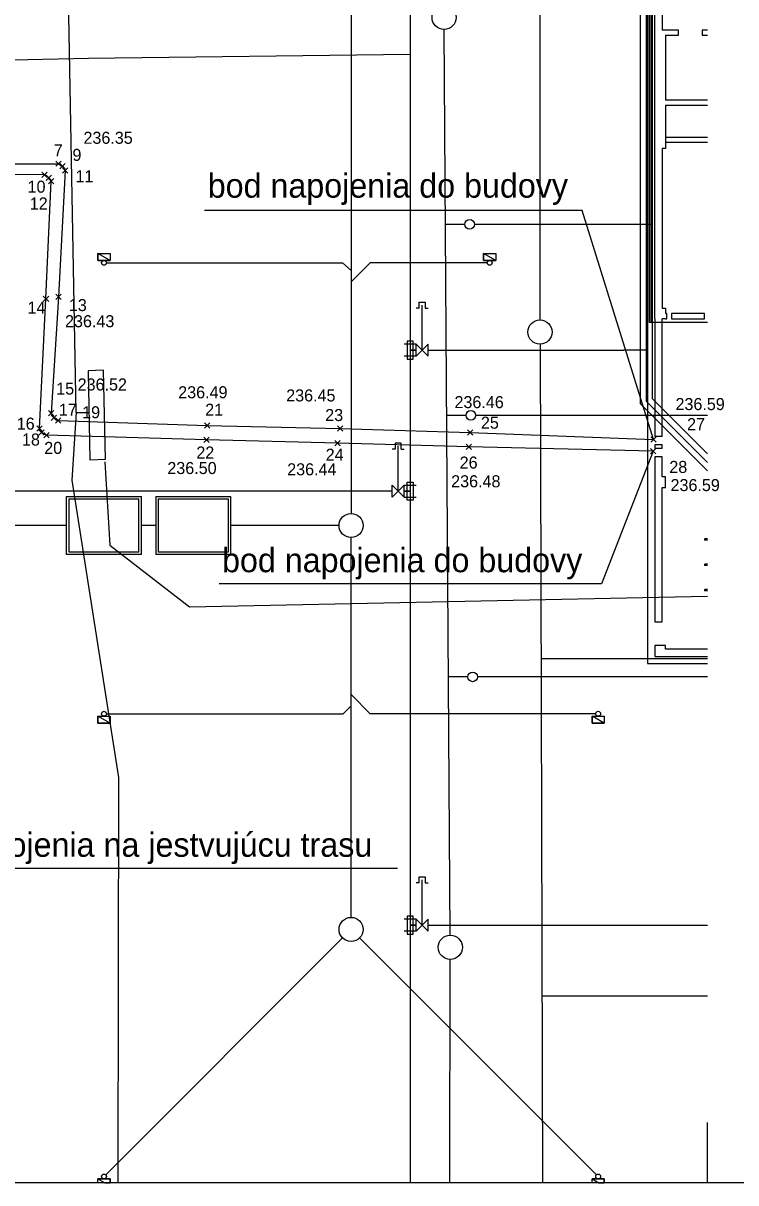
# Model space of a CAD drawing. Extents: x -263964 to -263859, y -1242287 to -1242158.
# Drawn here: x -263940.2 to -263910.63, y -1242232.02 to -1242183.91 of the extents above; entities that cross this region are included whole.
import ezdxf

# ---------------------------------------------------------------- set-up
doc = ezdxf.new("R2010")
doc.units = 0
for name, color, linetype in [('BODY_SYMBOL_A_CISLO', 7, 'Continuous'), ('BODY_VYSKA', 7, 'Continuous'), ('KFA_2D_JESTVUJUCE_IS_DSP', 7, 'Continuous'), ('KFA_2D_SITUACIA_DSP', 7, 'Continuous'), ('KFA_BETONY_HL_B_1PP', 7, 'Continuous'), ('KFA_SO_80-1_HORUCOVOD_TRASA', 7, 'Continuous'), ('POPIS', 7, 'Continuous'), ('RAM_NA_TLAC_A3_1-250', 7, 'Continuous')]:
    doc.layers.add(name, color=color, linetype=linetype)

msp = doc.modelspace()

# ---------------------------------------------------------------- linework, layer by layer
at = {"layer": 'BODY_SYMBOL_A_CISLO'}
for p, q in [((-263938.84, -1242189.85), (-263938.619, -1242189.63)), ((-263938.619, -1242189.85), (-263938.84, -1242189.63)), ((-263938.671, -1242189.951), (-263938.449, -1242189.73)), ((-263938.449, -1242189.951), (-263938.671, -1242189.73)), ((-263938.571, -1242190.13), (-263938.35, -1242189.91)), ((-263938.35, -1242190.13), (-263938.571, -1242189.91)), ((-263939.421, -1242190.311), (-263939.199, -1242190.09)), ((-263939.199, -1242190.311), (-263939.421, -1242190.09)), ((-263939.241, -1242190.441), (-263939.019, -1242190.22)), ((-263939.019, -1242190.441), (-263939.241, -1242190.22)), ((-263939.15, -1242190.58), (-263938.929, -1242190.36)), ((-263938.929, -1242190.58), (-263939.15, -1242190.36)), ((-263939.361, -1242195.458), (-263939.139, -1242195.237)), ((-263939.139, -1242195.458), (-263939.361, -1242195.237)), ((-263938.845, -1242195.382), (-263938.625, -1242195.16)), ((-263938.625, -1242195.382), (-263938.845, -1242195.16)), ((-263939.141, -1242200.201), (-263938.92, -1242199.98)), ((-263938.92, -1242200.201), (-263939.141, -1242199.98)), ((-263939.041, -1242200.39), (-263938.819, -1242200.17)), ((-263938.819, -1242200.39), (-263939.041, -1242200.17)), ((-263939.631, -1242200.84), (-263939.41, -1242200.62)), ((-263939.41, -1242200.84), (-263939.631, -1242200.62)), ((-263938.861, -1242200.511), (-263938.639, -1242200.289)), ((-263938.639, -1242200.511), (-263938.861, -1242200.289)), ((-263932.681, -1242200.711), (-263932.459, -1242200.49)), ((-263932.459, -1242200.711), (-263932.681, -1242200.49)), ((-263927.15, -1242200.84), (-263926.929, -1242200.62)), ((-263926.929, -1242200.84), (-263927.15, -1242200.62)), ((-263939.541, -1242201.011), (-263939.319, -1242200.789)), ((-263939.319, -1242201.011), (-263939.541, -1242200.789)), ((-263939.34, -1242201.11), (-263939.119, -1242200.89)), ((-263939.119, -1242201.11), (-263939.34, -1242200.89)), ((-263932.701, -1242201.311), (-263932.48, -1242201.09)), ((-263932.48, -1242201.311), (-263932.701, -1242201.09)), ((-263921.761, -1242201.011), (-263921.54, -1242200.789)), ((-263921.54, -1242201.011), (-263921.761, -1242200.789)), ((-263914.16, -1242201.301), (-263913.939, -1242201.079)), ((-263913.939, -1242201.301), (-263914.16, -1242201.079)), ((-263927.27, -1242201.451), (-263927.049, -1242201.23)), ((-263927.049, -1242201.451), (-263927.27, -1242201.23)), ((-263921.821, -1242201.6), (-263921.6, -1242201.38)), ((-263921.6, -1242201.6), (-263921.821, -1242201.38)), ((-263914.171, -1242201.781), (-263913.949, -1242201.559)), ((-263913.949, -1242201.781), (-263914.171, -1242201.559))]:
    msp.add_line(p, q, dxfattribs=at)
at = {"layer": 'KFA_2D_JESTVUJUCE_IS_DSP'}
for p, q in [((-263937.993, -1242200.068), (-263938.781, -1242157.773)), ((-263918.763, -1242157.773), (-263918.757, -1242196.225)), ((-263922.479, -1242221.753), (-263922.731, -1242184.174)), ((-263937.488, -1242185.363), (-263924.143, -1242185.192)), ((-263952.832, -1242185.692), (-263937.488, -1242185.363)), ((-263918.755, -1242197.225), (-263918.646, -1242232.023)), ((-263936.861, -1242198.305), (-263937.501, -1242198.334)), ((-263937.501, -1242198.334), (-263937.428, -1242202.028)), ((-263937.501, -1242198.334), (-263937.501, -1242198.334)), ((-263936.776, -1242202.003), (-263936.861, -1242198.305)), ((-263937.993, -1242200.068), (-263938.174, -1242202.878)), ((-263937.993, -1242200.068), (-263937.467, -1242200.068)), ((-263937.428, -1242202.028), (-263936.776, -1242202.003)), ((-263936.81, -1242202.117), (-263936.602, -1242205.569)), ((-263938.174, -1242202.878), (-263936.242, -1242215.207)), ((-263936.602, -1242205.569), (-263933.291, -1242208.127)), ((-263933.291, -1242208.127), (-263911.807, -1242207.682)), ((-263936.242, -1242215.207), (-263936.275, -1242232.023)), ((-263922.497, -1242232.023), (-263922.477, -1242222.753))]:
    msp.add_line(p, q, dxfattribs=at)
for centre in [(-263922.734, -1242183.674), (-263918.757, -1242196.725), (-263922.476, -1242222.253)]:
    msp.add_circle(centre, 0.5, dxfattribs=at)
at = {"layer": 'KFA_2D_SITUACIA_DSP'}
for p, q in [((-263926.593, -1242157.773), (-263926.593, -1242204.252)), ((-263924.143, -1242157.773), (-263924.143, -1242185.14)), ((-263914.218, -1242196.332), (-263914.218, -1242157.773)), ((-263914.143, -1242196.333), (-263914.143, -1242157.773)), ((-263914.6, -1242168.728), (-263914.6, -1242199.693)), ((-263914.35, -1242168.625), (-263914.35, -1242199.59)), ((-263914.1, -1242168.521), (-263914.1, -1242199.486)), ((-263914.293, -1242175.482), (-263914.293, -1242210.482)), ((-263924.143, -1242185.14), (-263924.143, -1242232.023)), ((-263921.877, -1242192.257), (-263922.677, -1242192.257)), ((-263915.293, -1242192.257), (-263921.477, -1242192.257)), ((-263914.143, -1242192.257), (-263915.293, -1242192.257)), ((-263937.093, -1242193.752), (-263937.093, -1242193.462)), ((-263937.093, -1242193.462), (-263936.593, -1242193.462)), ((-263936.593, -1242193.752), (-263937.093, -1242193.462)), ((-263936.593, -1242193.752), (-263937.093, -1242193.462)), ((-263937.093, -1242193.462), (-263937.093, -1242193.752)), ((-263936.593, -1242193.752), (-263937.093, -1242193.752)), ((-263937.093, -1242193.752), (-263936.593, -1242193.752)), ((-263936.743, -1242193.852), (-263926.953, -1242193.852)), ((-263936.593, -1242193.462), (-263936.593, -1242193.752)), ((-263926.953, -1242193.852), (-263926.593, -1242194.178)), ((-263925.798, -1242193.852), (-263926.593, -1242194.648)), ((-263920.944, -1242193.852), (-263925.798, -1242193.852)), ((-263921.093, -1242193.752), (-263921.093, -1242193.462)), ((-263921.093, -1242193.462), (-263920.593, -1242193.462)), ((-263920.593, -1242193.752), (-263921.093, -1242193.462)), ((-263920.593, -1242193.752), (-263921.093, -1242193.462)), ((-263921.093, -1242193.462), (-263921.093, -1242193.752)), ((-263920.593, -1242193.752), (-263921.093, -1242193.752)), ((-263921.093, -1242193.752), (-263920.593, -1242193.752)), ((-263920.593, -1242193.462), (-263920.593, -1242193.752)), ((-263923.768, -1242195.732), (-263923.893, -1242195.732)), ((-263923.768, -1242195.732), (-263923.768, -1242195.482)), ((-263923.768, -1242195.482), (-263923.518, -1242195.482)), ((-263923.643, -1242197.482), (-263923.643, -1242195.607)), ((-263923.518, -1242195.482), (-263923.518, -1242195.732)), ((-263923.518, -1242195.732), (-263923.393, -1242195.732)), ((-263911.807, -1242196.332), (-263914.218, -1242196.332)), ((-263911.807, -1242196.333), (-263914.143, -1242196.333)), ((-263923.893, -1242197.232), (-263924.393, -1242197.232)), ((-263924.018, -1242197.107), (-263924.268, -1242197.107)), ((-263924.268, -1242197.107), (-263924.268, -1242197.857)), ((-263924.018, -1242197.857), (-263924.018, -1242197.107)), ((-263923.893, -1242197.732), (-263923.893, -1242197.232)), ((-263923.893, -1242197.232), (-263923.393, -1242197.732)), ((-263923.393, -1242197.232), (-263923.893, -1242197.732)), ((-263923.393, -1242197.732), (-263923.393, -1242197.232)), ((-263923.893, -1242197.732), (-263924.393, -1242197.732)), ((-263924.143, -1242197.482), (-263923.893, -1242197.482)), ((-263923.893, -1242197.482), (-263924.143, -1242197.482)), ((-263923.393, -1242197.482), (-263915.293, -1242197.482)), ((-263914.293, -1242197.482), (-263915.293, -1242197.482)), ((-263924.268, -1242197.857), (-263924.018, -1242197.857)), ((-263914.6, -1242199.693), (-263911.807, -1242202.486)), ((-263914.35, -1242199.59), (-263911.807, -1242202.133)), ((-263914.1, -1242199.486), (-263911.807, -1242201.779)), ((-263921.824, -1242200.182), (-263922.624, -1242200.182)), ((-263915.293, -1242200.182), (-263921.424, -1242200.182)), ((-263911.807, -1242200.182), (-263915.293, -1242200.182)), ((-263924.768, -1242201.582), (-263924.893, -1242201.582)), ((-263924.768, -1242201.332), (-263924.768, -1242201.582)), ((-263924.518, -1242201.332), (-263924.768, -1242201.332)), ((-263924.643, -1242203.332), (-263924.643, -1242201.457)), ((-263924.518, -1242201.582), (-263924.518, -1242201.332)), ((-263924.518, -1242201.582), (-263924.393, -1242201.582)), ((-263924.268, -1242203.707), (-263924.268, -1242202.957)), ((-263924.268, -1242202.957), (-263924.018, -1242202.957)), ((-263924.018, -1242202.957), (-263924.018, -1242203.707)), ((-263924.893, -1242203.332), (-263958.097, -1242203.332)), ((-263938.393, -1242203.552), (-263935.293, -1242203.552)), ((-263938.393, -1242205.952), (-263938.393, -1242203.552)), ((-263935.293, -1242205.952), (-263935.293, -1242203.552)), ((-263934.693, -1242203.552), (-263931.593, -1242203.552)), ((-263934.693, -1242203.552), (-263934.693, -1242205.952)), ((-263931.593, -1242203.552), (-263931.593, -1242205.952)), ((-263924.893, -1242203.582), (-263924.893, -1242203.082)), ((-263924.393, -1242203.082), (-263924.893, -1242203.582)), ((-263924.893, -1242203.082), (-263924.393, -1242203.582)), ((-263924.393, -1242203.582), (-263924.393, -1242203.082)), ((-263924.393, -1242203.082), (-263923.893, -1242203.082)), ((-263924.143, -1242203.332), (-263924.393, -1242203.332)), ((-263924.393, -1242203.332), (-263924.143, -1242203.332)), ((-263938.293, -1242205.852), (-263938.293, -1242203.652)), ((-263938.293, -1242203.652), (-263935.393, -1242203.652)), ((-263935.393, -1242205.852), (-263935.393, -1242203.652)), ((-263934.593, -1242203.652), (-263934.593, -1242205.852)), ((-263934.593, -1242203.652), (-263931.693, -1242203.652)), ((-263931.693, -1242203.652), (-263931.693, -1242205.852)), ((-263924.393, -1242203.582), (-263923.893, -1242203.582)), ((-263924.018, -1242203.707), (-263924.268, -1242203.707)), ((-263938.393, -1242204.752), (-263942.945, -1242204.752)), ((-263934.693, -1242204.752), (-263935.293, -1242204.752)), ((-263927.093, -1242204.752), (-263931.593, -1242204.752)), ((-263926.593, -1242221.011), (-263926.593, -1242205.252)), ((-263911.807, -1242205.307), (-263911.913, -1242205.307)), ((-263911.807, -1242205.357), (-263911.913, -1242205.357)), ((-263935.293, -1242205.952), (-263938.393, -1242205.952)), ((-263935.393, -1242205.852), (-263938.293, -1242205.852)), ((-263931.593, -1242205.952), (-263934.693, -1242205.952)), ((-263931.693, -1242205.852), (-263934.593, -1242205.852)), ((-263911.807, -1242206.358), (-263911.913, -1242206.358)), ((-263911.807, -1242206.408), (-263911.913, -1242206.408)), ((-263911.807, -1242207.409), (-263911.913, -1242207.409)), ((-263911.807, -1242207.459), (-263911.913, -1242207.459)), ((-263911.807, -1242210.282), (-263918.714, -1242210.282)), ((-263914.293, -1242210.482), (-263911.807, -1242210.482)), ((-263921.751, -1242211.032), (-263922.551, -1242211.032)), ((-263911.807, -1242211.032), (-263921.351, -1242211.032)), ((-263925.798, -1242212.562), (-263926.593, -1242211.767)), ((-263937.093, -1242212.952), (-263937.093, -1242212.662)), ((-263937.093, -1242212.662), (-263936.593, -1242212.662)), ((-263936.593, -1242212.952), (-263937.093, -1242212.662)), ((-263936.593, -1242212.952), (-263937.093, -1242212.662)), ((-263937.093, -1242212.662), (-263937.093, -1242212.952)), ((-263936.743, -1242212.562), (-263926.919, -1242212.562)), ((-263936.593, -1242212.662), (-263936.593, -1242212.952)), ((-263926.919, -1242212.562), (-263926.593, -1242212.237)), ((-263916.443, -1242212.562), (-263925.798, -1242212.562)), ((-263916.593, -1242212.952), (-263916.593, -1242212.662)), ((-263916.593, -1242212.662), (-263916.093, -1242212.662)), ((-263916.093, -1242212.952), (-263916.593, -1242212.662)), ((-263916.093, -1242212.952), (-263916.593, -1242212.662)), ((-263916.593, -1242212.662), (-263916.593, -1242212.952)), ((-263916.093, -1242212.662), (-263916.093, -1242212.952)), ((-263936.593, -1242212.952), (-263937.093, -1242212.952)), ((-263937.093, -1242212.952), (-263936.593, -1242212.952)), ((-263916.093, -1242212.952), (-263916.593, -1242212.952)), ((-263916.593, -1242212.952), (-263916.093, -1242212.952)), ((-263923.768, -1242219.582), (-263923.768, -1242219.332)), ((-263923.768, -1242219.332), (-263923.518, -1242219.332)), ((-263923.518, -1242219.332), (-263923.518, -1242219.582)), ((-263923.768, -1242219.582), (-263923.893, -1242219.582)), ((-263923.643, -1242221.332), (-263923.643, -1242219.457)), ((-263923.518, -1242219.582), (-263923.393, -1242219.582)), ((-263923.893, -1242221.082), (-263924.393, -1242221.082)), ((-263924.018, -1242220.957), (-263924.268, -1242220.957)), ((-263924.268, -1242220.957), (-263924.268, -1242221.707)), ((-263924.143, -1242221.332), (-263923.893, -1242221.332)), ((-263923.893, -1242221.332), (-263924.143, -1242221.332)), ((-263924.018, -1242221.707), (-263924.018, -1242220.957)), ((-263923.893, -1242221.582), (-263923.893, -1242221.082)), ((-263923.893, -1242221.082), (-263923.393, -1242221.582)), ((-263923.393, -1242221.082), (-263923.893, -1242221.582)), ((-263923.393, -1242221.582), (-263923.393, -1242221.082)), ((-263923.393, -1242221.332), (-263911.807, -1242221.332)), ((-263923.893, -1242221.582), (-263924.393, -1242221.582)), ((-263924.268, -1242221.707), (-263924.018, -1242221.707)), ((-263936.772, -1242231.691), (-263926.947, -1242221.865)), ((-263916.414, -1242231.691), (-263926.24, -1242221.865)), ((-263911.807, -1242224.282), (-263918.67, -1242224.282)), ((-263937.093, -1242231.862), (-263936.593, -1242231.862)), ((-263937.093, -1242232.023), (-263937.093, -1242231.862)), ((-263937.093, -1242231.862), (-263936.814, -1242232.023)), ((-263936.593, -1242231.862), (-263937.093, -1242231.862)), ((-263937.093, -1242231.862), (-263936.814, -1242232.023)), ((-263936.593, -1242231.862), (-263936.593, -1242232.023)), ((-263936.593, -1242232.023), (-263936.593, -1242231.862)), ((-263916.593, -1242231.862), (-263916.093, -1242231.862)), ((-263916.593, -1242232.023), (-263916.593, -1242231.862)), ((-263916.593, -1242231.862), (-263916.314, -1242232.023)), ((-263916.093, -1242231.862), (-263916.593, -1242231.862)), ((-263916.593, -1242231.862), (-263916.314, -1242232.023)), ((-263916.093, -1242231.862), (-263916.093, -1242232.023)), ((-263916.093, -1242232.023), (-263916.093, -1242231.862)), ((-263936.814, -1242232.023), (-263936.593, -1242232.023)), ((-263916.314, -1242232.023), (-263916.093, -1242232.023))]:
    msp.add_line(p, q, dxfattribs=at)
for centre, radius in [((-263921.677, -1242192.257), 0.2), ((-263936.843, -1242193.852), 0.1), ((-263920.844, -1242193.852), 0.1), ((-263921.624, -1242200.182), 0.2), ((-263926.593, -1242204.752), 0.5), ((-263921.551, -1242211.032), 0.2), ((-263936.843, -1242212.562), 0.1), ((-263916.343, -1242212.562), 0.1), ((-263926.593, -1242221.511), 0.5), ((-263936.843, -1242231.762), 0.1), ((-263916.343, -1242231.762), 0.1)]:
    msp.add_circle(centre, radius, dxfattribs=at)
for centre, start, end in [((-263911.913, -1242205.332), 90, 270), ((-263911.913, -1242206.383), 90, 180), ((-263911.913, -1242206.383), 180, 270), ((-263911.913, -1242207.434), 90, 270)]:
    msp.add_arc(centre, 0.025, start, end, dxfattribs=at)
at = {"layer": 'KFA_BETONY_HL_B_1PP'}
for p, q in [((-263913.993, -1242188.657), (-263913.993, -1242182.107)), ((-263913.693, -1242182.107), (-263913.693, -1242184.207)), ((-263913.013, -1242184.207), (-263913.693, -1242184.207)), ((-263913.013, -1242184.407), (-263913.013, -1242184.207)), ((-263912.033, -1242184.207), (-263912.033, -1242184.407)), ((-263911.807, -1242184.207), (-263912.033, -1242184.207)), ((-263913.543, -1242184.407), (-263913.543, -1242187.107)), ((-263913.543, -1242184.407), (-263913.013, -1242184.407)), ((-263912.033, -1242184.407), (-263911.807, -1242184.407)), ((-263911.807, -1242187.107), (-263913.543, -1242187.107)), ((-263913.543, -1242187.307), (-263911.807, -1242187.307)), ((-263913.543, -1242187.307), (-263913.543, -1242188.657)), ((-263913.993, -1242189.107), (-263913.993, -1242188.657)), ((-263913.993, -1242195.732), (-263913.993, -1242189.107)), ((-263913.543, -1242189.107), (-263913.693, -1242189.107)), ((-263913.693, -1242189.107), (-263913.693, -1242195.732)), ((-263911.807, -1242188.657), (-263913.543, -1242188.657)), ((-263913.543, -1242188.657), (-263913.543, -1242189.107)), ((-263911.807, -1242188.857), (-263913.543, -1242188.857)), ((-263913.993, -1242196.182), (-263913.993, -1242195.732)), ((-263913.693, -1242195.732), (-263913.543, -1242195.732)), ((-263913.543, -1242195.732), (-263913.543, -1242195.957)), ((-263913.993, -1242196.182), (-263913.993, -1242196.182)), ((-263913.993, -1242196.182), (-263913.993, -1242197.407)), ((-263913.543, -1242196.182), (-263913.693, -1242196.182)), ((-263913.693, -1242197.407), (-263913.693, -1242196.182)), ((-263913.495, -1242195.957), (-263913.543, -1242195.957)), ((-263913.543, -1242196.182), (-263913.495, -1242196.182)), ((-263913.495, -1242196.182), (-263913.495, -1242195.957)), ((-263913.295, -1242195.957), (-263913.295, -1242196.182)), ((-263911.934, -1242195.957), (-263913.295, -1242195.957)), ((-263913.295, -1242196.182), (-263911.934, -1242196.182)), ((-263911.934, -1242196.182), (-263911.934, -1242195.957)), ((-263913.993, -1242197.407), (-263913.993, -1242197.557)), ((-263913.993, -1242197.557), (-263913.993, -1242201.057)), ((-263913.693, -1242197.557), (-263913.693, -1242197.407)), ((-263913.693, -1242201.057), (-263913.693, -1242197.557)), ((-263913.693, -1242201.057), (-263913.993, -1242201.057)), ((-263913.693, -1242201.407), (-263913.993, -1242201.407)), ((-263913.993, -1242201.407), (-263913.993, -1242201.557)), ((-263913.693, -1242201.557), (-263913.993, -1242201.557)), ((-263913.693, -1242201.557), (-263913.693, -1242201.407)), ((-263913.693, -1242201.907), (-263913.993, -1242201.907)), ((-263913.993, -1242201.907), (-263913.993, -1242202.732)), ((-263913.693, -1242202.732), (-263913.693, -1242201.907)), ((-263913.993, -1242202.732), (-263913.993, -1242203.182)), ((-263913.543, -1242202.732), (-263913.693, -1242202.732)), ((-263913.543, -1242203.182), (-263913.543, -1242202.732)), ((-263913.993, -1242203.182), (-263913.993, -1242208.742)), ((-263913.693, -1242203.182), (-263913.543, -1242203.182)), ((-263913.693, -1242208.742), (-263913.693, -1242203.182)), ((-263913.993, -1242208.742), (-263913.693, -1242208.742)), ((-263913.993, -1242209.732), (-263913.993, -1242210.182)), ((-263913.693, -1242209.732), (-263913.993, -1242209.732)), ((-263913.543, -1242209.732), (-263913.693, -1242209.732)), ((-263913.543, -1242209.882), (-263913.543, -1242209.732)), ((-263913.993, -1242210.182), (-263913.543, -1242210.182)), ((-263911.807, -1242209.882), (-263913.543, -1242209.882)), ((-263913.543, -1242210.182), (-263911.807, -1242210.182))]:
    msp.add_line(p, q, dxfattribs=at)
at = {"layer": 'KFA_SO_80-1_HORUCOVOD_TRASA'}
for points in [[(-263953.67, -1242189.74), (-263953.26, -1242189.76), (-263946.424, -1242189.748), (-263938.73, -1242189.74), (-263938.56, -1242189.84), (-263938.46, -1242190.02), (-263938.735, -1242195.271), (-263939.03, -1242200.09), (-263938.93, -1242200.28), (-263938.75, -1242200.4), (-263932.57, -1242200.6), (-263927.04, -1242200.73), (-263921.65, -1242200.9), (-263914.05, -1242201.19)], [(-263914.06, -1242201.67), (-263921.71, -1242201.49), (-263927.16, -1242201.34), (-263932.59, -1242201.2), (-263939.23, -1242201), (-263939.43, -1242200.9), (-263939.52, -1242200.73), (-263939.25, -1242195.347), (-263939.04, -1242190.47), (-263939.13, -1242190.33), (-263939.31, -1242190.2), (-263946.089, -1242190.162), (-263952.64, -1242190.15), (-263953.12, -1242190.16)]]:
    msp.add_lwpolyline(points, dxfattribs=at)
at = {"layer": 'POPIS'}
for p, q in [((-263917.009, -1242191.689), (-263932.669, -1242191.689)), ((-263914.047, -1242201.188), (-263917.009, -1242191.689)), ((-263914.059, -1242201.674), (-263916.2, -1242207.174)), ((-263916.2, -1242207.174), (-263932.06, -1242207.174)), ((-263945.951, -1242218.975), (-263924.667, -1242218.975))]:
    msp.add_line(p, q, dxfattribs=at)
at = {"layer": 'RAM_NA_TLAC_A3_1-250'}
msp.add_line((-263911.807, -1242232.023), (-263911.807, -1242229.523), dxfattribs=at)
msp.add_lwpolyline([(-263964.307, -1242157.773), (-263859.307, -1242157.773), (-263859.307, -1242232.023), (-263964.307, -1242232.023)], close=True, dxfattribs=at)

# ---------------------------------------------------------------- texts
at = {"layer": 'BODY_SYMBOL_A_CISLO'}
for s, p in [('7', (-263938.928, -1242189.439)), ('9', (-263938.152, -1242189.626)), ('11', (-263938.027, -1242190.511)), ('10', (-263940.014, -1242190.945)), ('12', (-263939.924, -1242191.642)), ('13', (-263938.302, -1242195.857)), ('14', (-263940.016, -1242195.961)), ('15', (-263938.826, -1242199.321)), ('17', (-263938.714, -1242200.198)), ('21', (-263932.646, -1242200.2)), ('19', (-263937.749, -1242200.304)), ('23', (-263927.667, -1242200.419)), ('16', (-263940.465, -1242200.776)), ('25', (-263921.207, -1242200.736)), ('27', (-263912.655, -1242200.797)), ('18', (-263940.246, -1242201.435)), ('20', (-263939.323, -1242201.782)), ('22', (-263933.012, -1242201.974)), ('24', (-263927.647, -1242202.064)), ('26', (-263922.088, -1242202.391)), ('28', (-263913.39, -1242202.571))]:
    msp.add_text(s, height=0.5, dxfattribs=at).set_placement(p)
at = {"layer": 'BODY_VYSKA'}
for s, p in [('236.35', (-263937.696, -1242188.916)), ('236.43', (-263938.46, -1242196.526)), ('236.52', (-263937.937, -1242199.151)), ('236.49', (-263933.765, -1242199.475)), ('236.45', (-263929.285, -1242199.605)), ('236.46', (-263922.304, -1242199.883)), ('236.59', (-263913.135, -1242199.964)), ('236.50', (-263934.216, -1242202.617)), ('236.44', (-263929.244, -1242202.671)), ('236.48', (-263922.441, -1242203.167)), ('236.59', (-263913.34, -1242203.325))]:
    msp.add_text(s, height=0.5, dxfattribs=at).set_placement(p)
at = {"layer": 'POPIS'}
for s, p in [('bod napojenia do budovy', (-263932.54, -1242191.15)), ('bod napojenia do budovy', (-263931.946, -1242206.69)), ('bod napojenia na jestvujúcu trasu', (-263945.637, -1242218.497))]:
    msp.add_text(s, height=1, dxfattribs=at).set_placement(p)

doc.saveas('drawing.dxf')
